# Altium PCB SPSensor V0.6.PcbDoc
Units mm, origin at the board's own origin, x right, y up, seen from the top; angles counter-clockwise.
Board outline 97.48 x 57.45 mm, 4 copper layers (TopLayer, GND, PWR, BottomLayer); 106 components, 63 nets, 343 pads, 148 vias.
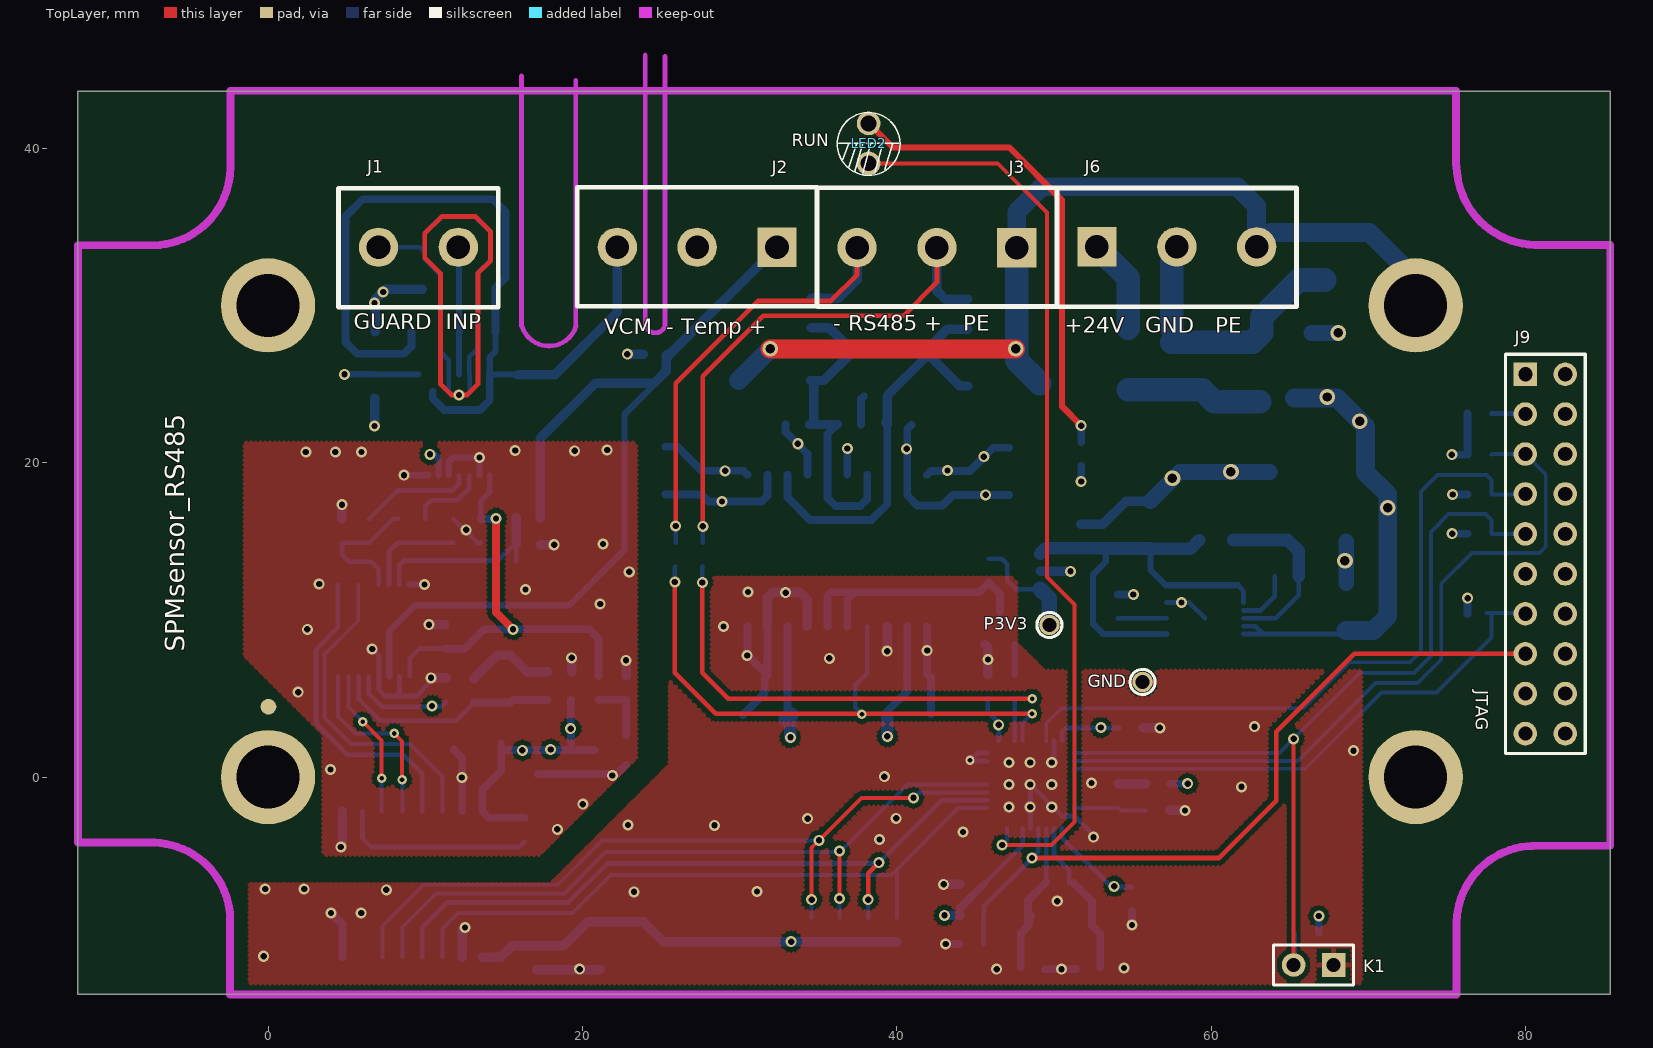
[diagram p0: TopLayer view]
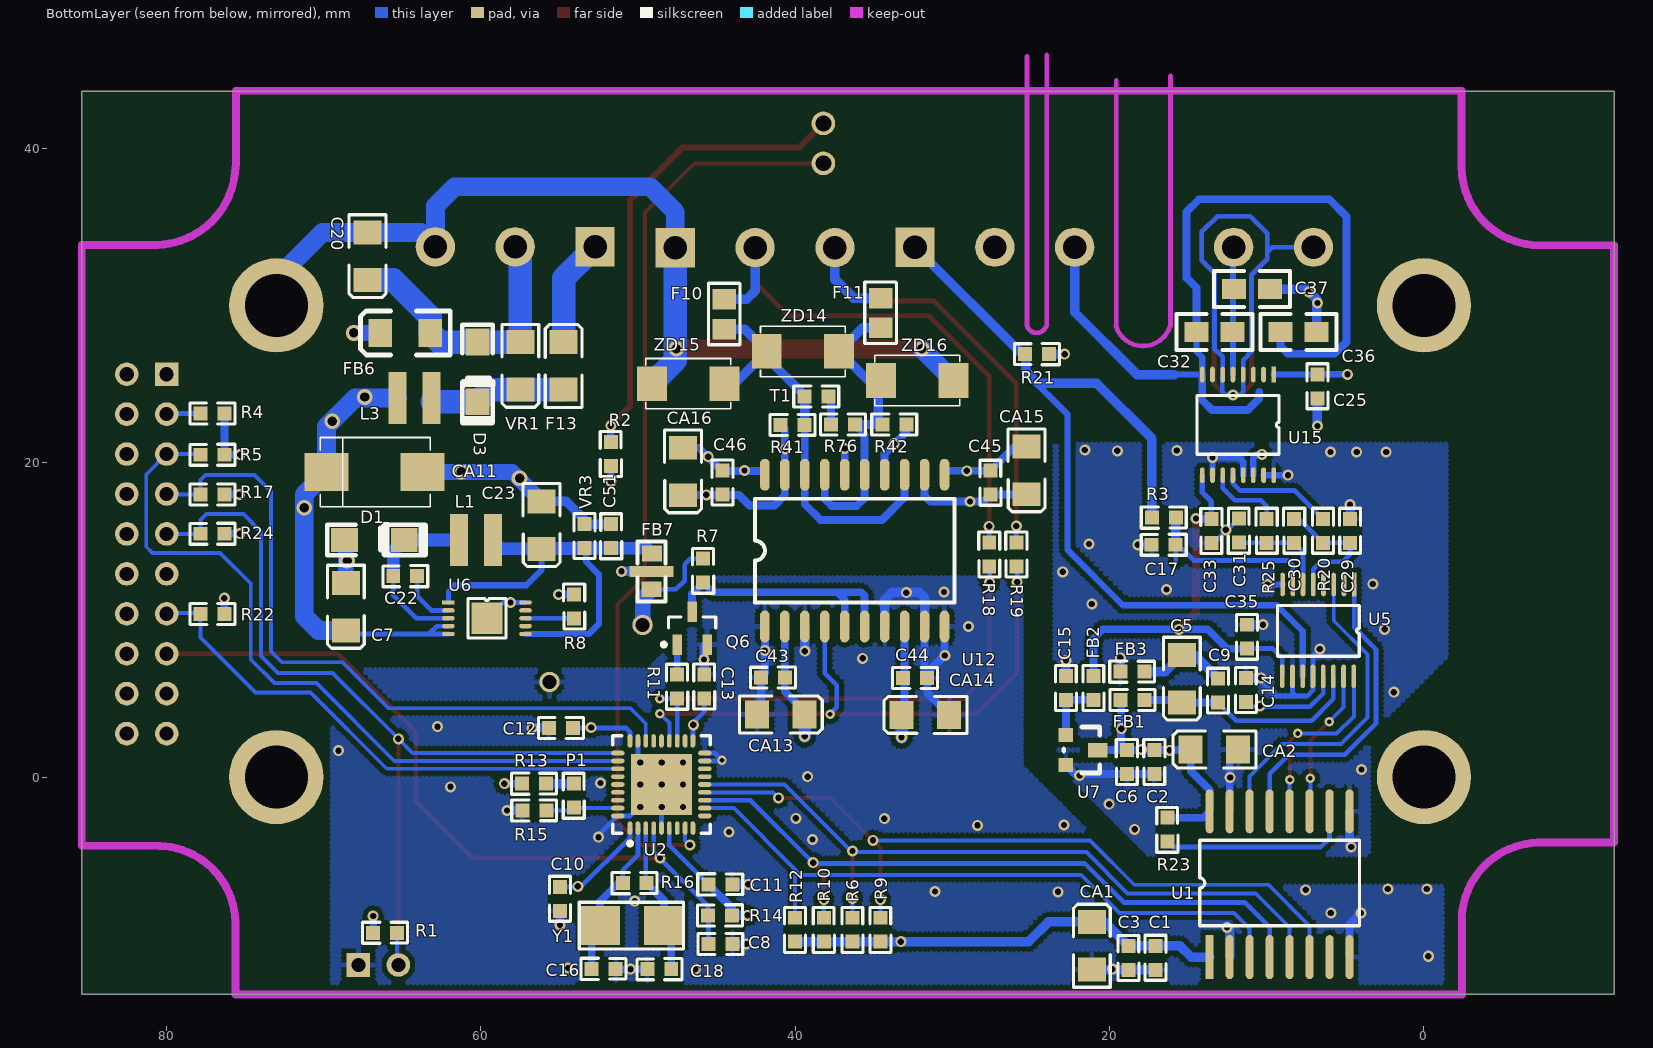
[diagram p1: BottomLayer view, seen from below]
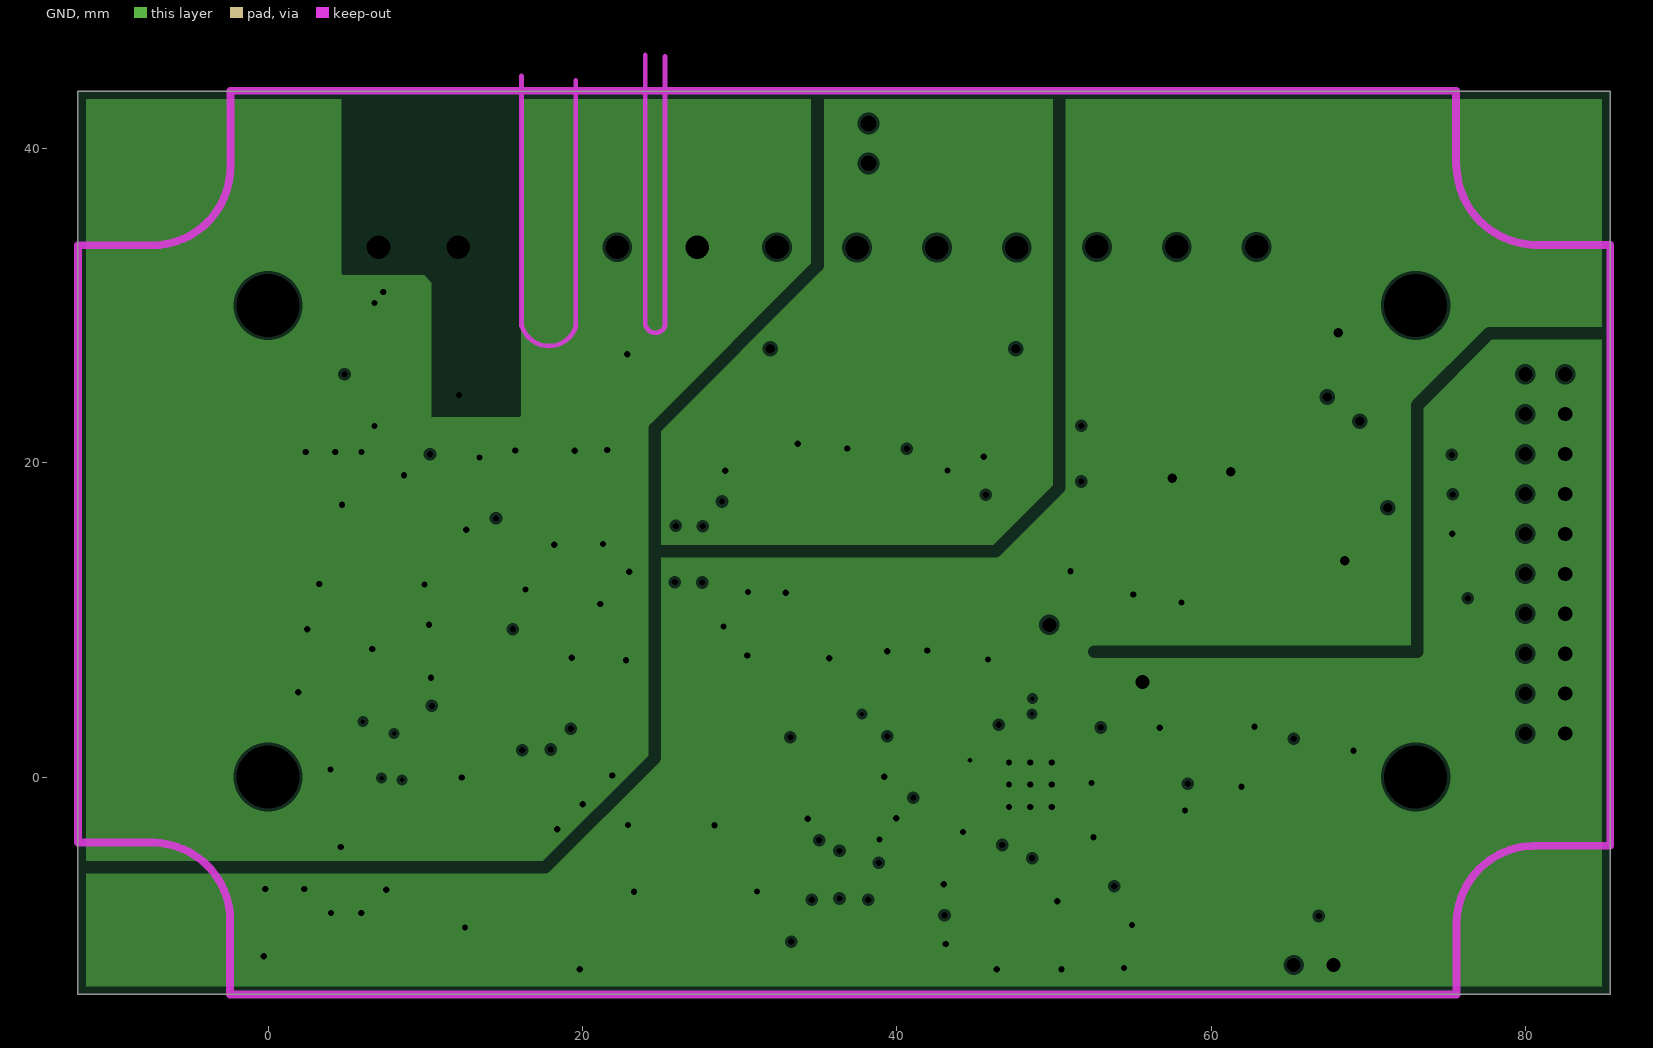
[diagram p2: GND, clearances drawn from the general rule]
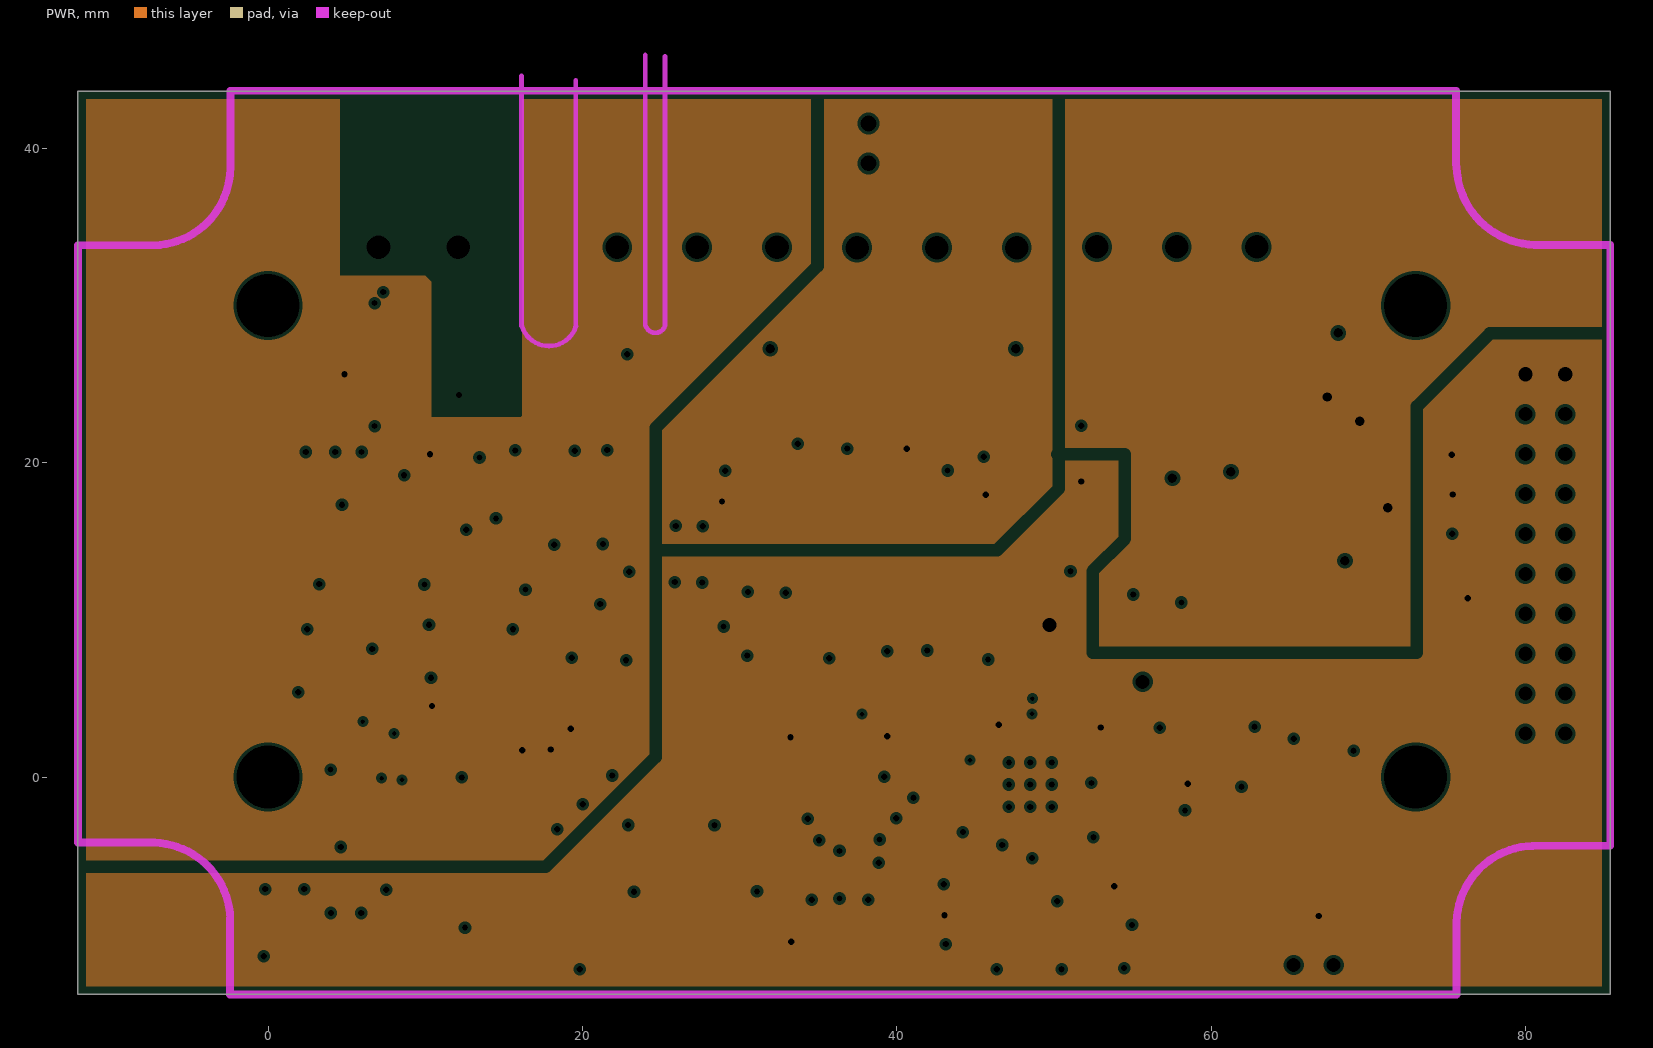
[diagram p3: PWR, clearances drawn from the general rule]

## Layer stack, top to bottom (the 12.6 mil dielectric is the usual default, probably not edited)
TopLayer: signal copper 0.0356
Dielectric: core 0.32, FR-4, Dk 4.8
GND: plane copper 0.0356, net (Multiple Nets)
Dielectric: prepreg 0.32, FR-4, Dk 4.8
PWR: plane copper 0.0356, net (Multiple Nets)
Dielectric: core 0.32, FR-4, Dk 4.8
BottomLayer: signal copper 0.0356

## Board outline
-12.1,-13.825 85.375,-13.825 85.375,43.625 -12.1,43.625

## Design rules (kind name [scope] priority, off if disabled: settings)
Clearance Clearance_poly [InPolygon] p1: gap=0.3
Clearance [All] p2: gap=0.15
ComponentClearance [All] p1: gap=0.15 collisioncheckmode=3 verticalgap=0.254 showdistances=FALSE
FabricationTestPointUsage TestPointUsage [All] p1: valid=0 allowmultiple=FALSE
FabricationTestpoint Testpoint [All] p1: side=3 testpointundercomponent=TRUE minsize=1.016 maxsize=2.54 preferedsize=1.524 minholesize=0.508 maxholesize=1.016 preferedholesize=0.813 testpointgrid=0.025 allowsidetop=TRUE allowsidebottom=TRUE usegrid=TRUE gridtolerance=0
HoleSize [All] p1: absolutevalues=TRUE maxlimit=10 minlimit=0.025 maxpercent=80.000 minpercent=20.000
MinimumSolderMaskSliver [All] p1: minsoldermaskwidth=0.15
PlaneClearance [All] p1: clearance=0.2
PlaneConnect [All] p1: planeconnectstyle=Relief reliefexpansion=0.3 reliefentries=4 reliefconductorwidth=0.3 reliefairgap=0.3
PolygonConnect PolygonConnect_via [IsVia] p1: connectstyle=Direct reliefconductorwidth=0.254 reliefentries=4 polygonreliefangle="90 Angle"
PolygonConnect [All] p2: connectstyle=Relief reliefconductorwidth=0.3 reliefentries=4 polygonreliefangle="90 Angle"
RoutingVias [All] p1: holewidth=0.305 width=0.61 viastyle="Through Hole" minholewidth=0.254 minwidth=0.508 maxholewidth=2 maxwidth=5
SilkToSilkClearance [All] p1: silktosilkclearance=0
SilkscreenOverComponentPads [All] p1: minsilkscreentomaskgap=0
SolderMaskExpansion [All] p1: expansion=0.102
Width [All] p1: maxlimit=5.08 minlimit=0.1 preferedwidth=0.254
19 further rules are at their usual default settings.

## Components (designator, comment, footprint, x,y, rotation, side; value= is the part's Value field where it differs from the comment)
C1 "10nF" SM0603 17.025,-11.5 r270 bottom
C2 "0.1uF" SM0603 17.1,0.95 r270 bottom
C3 "0.1uF" SM0603 18.85,-11.5 r90 bottom
C5 "10uF" SM1206 15.4,6.25 r270 bottom
C6 "4.7uF" SM0603 18.85,0.95 r270 bottom
C7 "4.7uF/50V" SM1206 68.575,10.825 r270 bottom
C8 "0.1uF" SM0603 44.75,-10.575 r180 bottom
C9 "0.1uF" SM0603 13.15,5.5 r90 bottom
C10 "0.1uF" SM0603 54.905,-7.75 r270 bottom
C11 "0.1uF" SM0603 44.755,-6.775 r180 bottom
C12 "0.1uF" SM0603 54.9,3.075 r0 bottom
C13 "0.1uF" SM0603 45.83,5.765 r90 bottom
C14 "0.1uF" SM0603 11.375,5.55 r90 bottom
C15 "1uF" SM0603 22.825,5.675 r90 bottom
C16 "22pF" SM0603 52.175,-12.15 r180 bottom
C17 "1uF" SM0603 16.555,14.725 r0 bottom
C18 "22pF" SM0603 48.64,-12.275 r0 bottom
C20 "1nF/2kV" SM1206 67.2,33.125 r270 bottom
C22 "0.47uF" SM0603 64.8,12.725 r0 bottom
C23 "22uF" SM1206 56.125,16.025 r270 bottom
C25 "0.1uF" SM0603 6.725,24.85 r270 bottom
C29 "1uF" SM0603 4.65,15.66 r270 bottom
C30 "100pF" SM0603 8.2,15.66 r270 bottom
C31 "1uF" SM0603 11.825,15.675 r90 bottom
C32 "1nF/2kV" 0805 12.175,28.325 r0 bottom (schematic designator C4)
C33 "0.1uF" SM0603 13.475,15.65 r270 bottom
C35 "0.1uF" SM0603 11.3,8.925 r90 bottom
C36 "1nF" 0805 9.125,28.3 r180 bottom (schematic designator C21)
C37 "1nF" 0805 12.1,31.025 r180 bottom (schematic designator C19)
C43 "0.1uF" SM0603 41.415,6.275 r0 bottom
C44 "0.1uF" SM0603 32.36,6.35 r180 bottom
C45 "0.1uF" SM0603 27.625,18.725 r90 bottom
C46 "0.1uF" SM0603 44.575,18.725 r270 bottom
C51 "0.1uF" SM0603 51.75,15.325 r90 bottom
CA1 "10uF" SM1206 21.125,-10.725 r90 bottom
CA2 "10uF" SM1206 13.325,1.75 r0 bottom
CA11 "47uF/50V" D 69.8,19.4 r180 bottom
CA13 "10uF" SM1206 40.9,3.975 r180 bottom
CA14 "10uF" SM1206 31.715,3.95 r0 bottom
CA15 "10uF" SM1206 25.275,19.5 r270 bottom
CA16 "10uF" SM1206 47.125,19.435 r270 bottom
D1 "CD1607-B140" 1206D 68.467,15.075 r180 bottom
D3 "1N4007" 1206D 60.2,27.475 r270 bottom
F10 "FUSE1" SM0805 44.475,29.425 r90 bottom
F11 "FUSE1" SM0805 34.525,29.5 r90 bottom
F13 "1A" SM1206 54.725,26.15 r90 bottom
FB1 "BLM18PG600SN1" SM0603 18.525,4.95 r180 bottom
FB2 "BLM18PG600SN1" SM0603 21.075,5.675 r90 bottom
FB3 "BLM18PG600SN1" SM0603 18.55,6.75 r180 bottom
FB6 "BLM31PG500SN1" 1206 66.25,28.25 r0 bottom
FB7 "NFM21PC105B1C3" NFM21PC105 49.125,14.225 r270 bottom
GND "TestPoint" "test point" 55.625,6.05 r90 top
J1 "PH2-5.08mm" PH2-5.08mm 7.025,33.7 r0 top
J2 "PH3-5.08mm" PH3-5.08mm 32.375,33.7 r180 top
J3 "PH3-5.08mm" PH3-5.08mm 47.625,33.675 r180 top
J6 "PH3-5.08mm" PH3-5.08mm 52.725,33.725 r0 top
J9 "JTAG" HDR2X10 79.975,25.625 r270 top
K1 "KEY1" HDR1x2 67.775,-11.955 r180 top (schematic designator R1)
L1 "LPS3010-472ML" LPS3010 61.385,15.075 r180 bottom
L3 "LPS3010-472ML" LPS3010 63.125,24.1 r0 bottom
LED2 "RUN" LED 38.2,41.575 r270 top
P1 "NC" sm0603 54.13,-1.185 r90 bottom
P3V3 "TestPoint" "test point" 49.7,9.675 r90 top
Q6 "MMBT3904" SOT23_N 46.55,9.475 r90 bottom
R1 "10K" SM0603 66.075,-9.855 r180 bottom
R2 "560R" SM0603 51.775,20.55 r90 bottom
R3 "10K" SM0603 16.54,16.55 r180 bottom
R4 "10K" SM0603 77.065,23.075 r0 bottom
R5 "10K" SM0603 77.065,20.45 r0 bottom
R6 "100K" SM0603 36.401,-9.713 r90 bottom
R7 "4.7K" SM0603 45.9,13.125 r90 bottom
R8 "49.9K" SM0603 54,10.85 r270 bottom
R9 "100K" SM0603 34.626,-9.713 r90 bottom
R10 "100K" SM0603 38.226,-9.713 r90 bottom
R11 "1K" SM0603 47.555,5.75 r90 bottom
R12 "100K" SM0603 40.051,-9.713 r90 bottom
R13 "1K" SM0603 56.605,-0.375 r180 bottom
R14 "10K" SM0603 44.775,-8.85 r0 bottom
R15 "100K" SM0603 56.59,-2.075 r180 bottom
R16 "10M" SM0603 50.2,-6.7 r180 bottom
R17 "10K" SM0603 77.065,17.925 r0 bottom
R18 "0R" SM0603 27.6,14.15 r270 bottom
R19 "0R" SM0603 25.875,14.15 r270 bottom
R20 "10K" SM0603 6.375,15.66 r270 bottom
R21 "NC" SM0603 24.625,26.85 r0 bottom
R22 "10K" SM0603 77.065,10.325 r0 bottom
R23 "4.7K" SM0603 16.375,-3.35 r90 bottom
R24 "NC" SM0603 77.065,15.425 r0 bottom
R25 "10K" SM0603 9.95,15.66 r270 bottom
R41 "47K" SM0603 40.16,22.45 r180 bottom
R42 "47K" SM0603 33.685,22.475 r180 bottom
R76 "120R" SM0603 36.965,22.375 r0 bottom
T1 "" SM0603 38.65,24.25 r180 bottom
U1 "ADuM5401ARWZ" ADUM1401 13.625,-11.45 r90 bottom locked
U2 "STM32F103T8U6" VFQN36_V 48.5,-0.475 r90 bottom locked
U5 "AD7793BRU" AD7793 6.725,9.325 r270 bottom
U6 "LT3971IMSE-3.3" LT3971 59.6,10.1 r270 bottom
U7 "AD1584BRTZ" SOT-23 20.63,0.339 r270 bottom
U12 "ADM2587E" SOL-20 41.925,9.575 r90 bottom
U15 "LMP91200" LMP91200 11.825,22.4 r0 bottom
VR1 "V42MLA1206N" SM1206 57.475,26.15 r270 bottom
VR3 "V3.5MLA0603N" SM0603 53.35,15.325 r270 bottom (schematic designator VA2)
Y1 "8MHz" CY5.4X4.6 52.375,-9.45 r180 bottom
ZD14 "SMBJ12" ZD 41.8,27.075 r180 bottom
ZD15 "SMBJ12" ZD 44.5,25.025 r0 bottom
ZD16 "SMBJ12" ZD 29.925,25.225 r0 bottom

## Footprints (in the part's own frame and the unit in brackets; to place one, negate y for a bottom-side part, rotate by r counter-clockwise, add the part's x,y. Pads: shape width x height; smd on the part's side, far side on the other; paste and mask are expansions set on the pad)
0805 [mil]
  rect 60x50 smd: 1(0.39,0.31) 2(90.39,0.31)
  silkscreen extent -50,-45 140,45
1206 [mm]
  rect 1.5x1.8 smd: 1(-3.048,0) 2(0.127,0)
  silkscreen extent -4.32,-1.4 1.4,1.4
1206D [mm]
  rect 1.7x1.524 smd: 1(-0.19,0.003) 2(3.61,0.003)
  silkscreen extent -1.3,-0.97 4.96,0.99
AD7793 [mm]
  rect 1.5x0.3 smd: 1(-2.921,2.286)
  oval 1.5x0.3 smd: 2(-2.921,1.636) 3(-2.921,0.986) 4(-2.921,0.336) 5(-2.921,-0.314) 6(-2.921,-0.964) 7(-2.921,-1.614) 8(-2.921,-2.264) 9(2.921,-2.286) 10(2.921,-1.636) 11(2.921,-0.986) 12(2.921,-0.336) 13(2.921,0.314) 14(2.921,0.964) 15(2.921,1.614) 16(2.921,2.264)
  silkscreen extent -1.59,-2.59 1.64,2.61
ADUM1401 [mm]
  rect 2.8x0.51 smd: 1(0,0)
  oval 2.8x0.51 smd: 2(0,-1.27) 3(0,-2.54) 4(0,-3.81) 5(0,-5.08) 6(0,-6.35) 7(0,-7.62) 8(0,-8.89) 9(9.271,-8.89) 10(9.271,-7.62) 11(9.271,-6.35) 12(9.271,-5.08) 13(9.271,-3.81) 14(9.271,-2.54) 15(9.271,-1.27) 16(9.271,0)
  silkscreen extent 1.99,-9.53 7.43,0.63
CY5.4X4.6 [mm]
  rect 2.5x2.5 smd: 1(-0.025,0) 2(4,0)
  silkscreen extent -1.35,-1.49 5.28,1.49
D [mil]
  rect 110x94.49 smd: 1(0,0) 2(240,0)
  silkscreen extent -16,-87 260,87
HDR1x2 [mm] "Connector; Header; 2 Position"
  rect 1.5x1.5 hole 0.9: 1(0,0)
  round 1.5 hole 0.9: 2(2.54,0)
  silkscreen extent -1.27,-1.27 3.81,1.27
HDR2X10 [mm] "Connector; Header; 10x2 Position"
  rect 1.5x1.5 hole 0.9: 1(0,0)
  round 1.5 hole 0.9: 2(0,2.54) 3(2.54,0) 4(2.54,2.54) 5(5.08,0) 6(5.08,2.54) 7(7.62,0) 8(7.62,2.54) 9(10.16,0) 10(10.16,2.54) 11(12.7,0) 12(12.7,2.54) 13(15.24,0) 14(15.24,2.54) 15(17.78,0) 16(17.78,2.54) 17(20.32,0) 18(20.32,2.54) 19(22.86,0) 20(22.86,2.54)
  silkscreen extent -1.27,-1.27 24.13,3.81
LED [mm]
  round 1.5 hole 1: 1(0,0) 2(2.54,0)
  silkscreen extent -0.7,-2 3.3,2
LMP91200 [mm]
  rect 0.3x1 smd: 1(-2.275,-3.2)
  oval 0.3x1 smd: 2(-1.625,-3.2) 3(-0.975,-3.2) 4(-0.325,-3.2) 5(0.325,-3.2) 6(0.975,-3.2) 7(1.625,-3.2) 8(2.275,-3.2) 9(2.275,3.2) 10(1.625,3.2) 11(0.975,3.2) 12(0.325,3.2) 13(-0.325,3.2) 14(-0.975,3.2) 15(-1.625,3.2) 16(-2.275,3.2)
  silkscreen extent -2.6,-1.87 2.6,1.87
LPS3010 [mm]
  rect 1.14x3.3 smd: 1(0,0) 2(2.16,0)
LT3971 [mm]
  rect 0.28x0.8 smd: 1(-1,-2.45)
  oval 0.28x0.8 smd: 2(-0.5,-2.45) 3(0,-2.45) 4(0.5,-2.45) 5(1,-2.45) 6(1,2.45) 7(0.5,2.45) 8(0,2.45) 9(-0.5,2.45) 10(-1,2.45)
  rect 2x2 smd: 11(0,0)
  silkscreen extent -1.25,-1.21 1.25,1.22
NFM21PC105 [mm]
  rect 1x1.27 smd: 1(0.01,0.008) 2(2.286,0)
  rect 0.7x2.8 smd: 3(1.143,0)
  silkscreen extent -0.76,-0.89 3.05,0.89
PH2-5.08mm [mm]
  round 2.5 hole 1.5: 1(0,0) 2(5.08,0)
  silkscreen extent -2.54,-3.81 7.62,3.75
PH3-5.08mm [mm]
  rect 2.5x2.5 hole 1.5: 1(0,0)
  round 2.5 hole 1.5: 2(5.08,0) 3(10.16,0)
  silkscreen extent -2.54,-3.81 12.7,3.75
SM0603 [mil]
  rect 35x35 smd: 1(-30,-2) 2(30,-2)
  silkscreen extent -57,-28 56,24
sm0603 [mil]
  rect 35x35 smd: 1(-30,-2) 2(30,-2)
  silkscreen extent -57,-28 56,24
SM0805 [mm]
  rect 1.3x1.5 smd: 1(-0.933,0.022) 2(0.967,0.022)
  silkscreen extent -1.93,-0.97 1.98,1.04
SM1206 [mil]
  rect 60x70 smd: 1(59.5,0) 2(-59.5,0)
  silkscreen extent -104,-46 104,46
SOL-20 [mil]
  oval 80x24 smd: 1(0,0) 2(0,-50) 3(0,-100) 4(0,-150) 5(0,-200) 6(0,-250) 7(0,-300) 8(0,-350) 9(0,-400) 10(0,-450) 11(380,-450) 12(380,-400) 13(380,-350) 14(380,-300) 15(380,-250) 16(380,-200) 17(380,-150) 18(380,-100) 19(380,-50) 20(380,0)
  silkscreen extent 60,-475 320,25
SOT23_N [mm] "SOT23, 3-Leads, Body 2.9x1.3mm, Pitch 0.95mm, Lead Span 2.3mm, IPC Medium Density"
  rect 1.3x0.6 smd: 1(-1.05,0.95) 2(-1.05,-0.95) 3(1.05,0)
  silkscreen extent -1.17,-1.5 0.7,1.93, body extent -0.7,-1.5 0.7,1.5, height 1.1
SOT-23 [mil]
  rect 36x36 smd: 1(-91.86,-84.66) 2(-16.86,-84.66)
  rect 36x50 smd: 3(-53.86,-4.66)
  silkscreen extent -112,-90 3,0
"test point" [mm]
  round 1.3 hole 0.9: 1(0,0)
  silkscreen extent -0.8,-0.8 0.8,0.8
VFQN36_V [mm] "QFN, 36-Leads, Body 6x6mm, Pitch 0.5mm, ST Recommended"
  oval 0.85x0.3 smd: 1(-2.775,2) 2(-2.775,1.5) 3(-2.775,1) 4(-2.775,0.5) 5(-2.775,0) 6(-2.775,-0.5) 7(-2.775,-1) 8(-2.775,-1.5) 9(-2.775,-2) 19(2.775,-2) 20(2.775,-1.5) 21(2.775,-1) 22(2.775,-0.5) 23(2.775,0) 24(2.775,0.5) 25(2.775,1) 26(2.775,1.5) 27(2.775,2)
  oval 0.3x0.85 smd: 10(-2,-2.755) 11(-1.5,-2.755) 12(-1,-2.755) 13(-0.5,-2.755) 14(0,-2.755) 15(0.5,-2.755) 16(1,-2.755) 17(1.5,-2.755) 18(2,-2.755) 28(2,2.775) 29(1.5,2.775) 30(1,2.775) 31(0.5,2.775) 32(0,2.775) 33(-0.5,2.775) 34(-1,2.775) 35(-1.5,2.775) 36(-2,2.775)
  rect 3.9x3.9 smd: 37(0,0)
  silkscreen extent -3.87,-3.1 3.1,3.1, body extent -3.05,-3.05 3.05,3.05, height 1
ZD [mm]
  rect 1.9x2.2 smd: 1(0,0) 2(4.6,0)
  silkscreen extent -0.4,-1.6 5,1.6

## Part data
C1 C6 C7 C9 C14 C15 C17 C20 C22 C25 C29 C30 C31 C32 C33 C35 C36 C37 C51: library part CAP, "Capacitor"
C2 C3 C43 C44 C45 C46: library part CAP, "电?"
C5 CA11 CA13 CA14 CA15 CA16: library part CAPE, "极性"
C8: library part Cap, "Capacitor, X7R Ceramic"
C10 C11 C12 C13 C16 C18: library part Cap, "Capacitor"
C23: library part C, "极性"
CA1 CA2: library part CAPE, "Capacitor"
D1: library part DIODE, "Diode"
D3: library part "Diode 1N4007", "1 Amp General Purpose Rectifier"
F10 F11: "Fuse"
F13: library part FUSE1, "Fuse"
FB1 FB3 L1 L3: library part INDUCTOR
FB2 FB6 FB7: library part Inductor, "Inductor"
J1 K1: library part "Header 2", "Header, 2-Pin"
J2 J3 J6: library part CON3, "Connector"
J9: library part "Header 10X2", "Header, 10-Pin, Dual row"
LED2: library part LED0, "Typical INFRARED GaAs LED"
P1: library part Hea, "Header, 2-Pin, 2.54mm, 排?"
Q6: "NPN Switching Transistor"
R1 R2 R7 R11 R16 R18 R19: library part Res2, "Resistor"
R3 R4 R5 R6 R9 R10 R12 R17 R20 R21 R22 R24 R25: library part R, "电?"
R8 R13 R14 R15 R23 R41 R42 R76: library part RES, "电?"
T1: library part CON2, "Connector"
U1: library part ADUM1401, "1Mbps Data Rate, 100ns Propagation delay"
U2: "STM32 ARM-based 32-bit MCU with 64 Kbytes Flash, 36-pin VFQFPN, Industrial Temperature"
U5: library part AD7793
U6: library part LT3971
U7: library part "Header 3", "4.096V reference"
VR1: library part "Res Varistor", "Varistor (Voltage-Sensitive Resistor)"
VR3: library part "D Zener", "Zener Diode"
Y1: library part XTAL, "Crystal Oscillator"
ZD14 ZD15 ZD16: library part SMBJ, "Ë²±äÒ"

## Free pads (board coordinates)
  round 1 smd: 0(0.025,4.475)
  round 6 hole 4: 3(73,30) 4(73,0) 5(0,0) 6(0,30)

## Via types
v1: diameter 0.7, hole 0.4, TopLayer to BottomLayer, 131 vias
v2: diameter 1, hole 0.6, TopLayer to BottomLayer, 9 vias
v3: diameter 0.6, hole 0.3, TopLayer to BottomLayer, 8 vias

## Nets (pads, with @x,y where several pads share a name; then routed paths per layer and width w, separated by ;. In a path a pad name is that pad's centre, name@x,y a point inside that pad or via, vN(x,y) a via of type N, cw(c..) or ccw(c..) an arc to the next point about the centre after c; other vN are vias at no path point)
24VGND_IN: C20.1 D3.1 FB6.1 J6.2 VR1.2 | length 17.8
  BottomLayer w1.5: VR1.2 60.193,27.661 D3.1 62.617,27.665 FB6.1 63.202,29.252 65.564,31.614 C20.1 ; 57.475,28.536 57.475,33.395 J6.2 J6.2@58.147,33.383
+24V: C7.1 CA11.1 L3.2 U6.4 U6.5 | length 29
  BottomLayer w0.3: U6.5 63.3,9.1 ; U6.4 62.8,9.6 63.3,9.1 ; C7.1 68.361,9.1 63.3,9.1
  BottomLayer w1.2: L3.2 68,24.1 69.8,22.3 CA11.1 71.225,17.975 71.225,10.225 70.314,9.314 C7.1
  other v2: 71.225,17.125 69.45,22.625 67.375,24.175
+24V_IN: F13.1 J6.1 | length 6.1
  BottomLayer w1.5: J6.1@52.675,33.675 J6.1 54.725,31.725 54.725,28.536
BOOT0: P1.1 R15.2 U2.35 | length 4.6
  BottomLayer w0.25: U2.35 54.052,-1.975 P1.1 54.258,-2.126 R15.2
DE485: Q6.3 R7.1 U12.5 U12.6 | length 17.1
  BottomLayer w0.5: U12.6 35.575,11.525 35.8,11.75 37.325,11.75 ; U12.5 36.845,11.27 37.325,11.75 ; Q6.3 46.55,11.662 R7.1 45.236,11.75 37.325,11.75
DVDD: C5.1 C9.1 FB1.2 U5.14 | length 14.6
  BottomLayer w0.3: U5.14 5.761,4.964 7.15,3.575 11.936,3.575 C9.1
  BottomLayer w0.5: C9.1 C5.1 15.561,4.899 FB1.2
EARTH: C20.2 J3.1 J6.3 pad.3 ZD15.2 ZD16.1 | length 62.5
  TopLayer w1.2: v2(31.938,27.237) v2(47.562,27.237)
  BottomLayer w1.2: ZD16.1 v2(31.938,27.237) ; J3.1 47.625,35.95 49.225,37.55 61.65,37.55 62.885,36.315 J6.3 63.796,34.636 C20.2 70.064,34.636 73,31.7 pad.3
  BottomLayer w1.5: J3.1@47.675,33.625 J3.1 47.625,26.5 ZD15.2
GND: C1.2 C3.1 C7.2 C8.2 C10.2 C11.2 C12.2 C13.2 C16.2 C18.2 C23.2 C43.2 C44.2 C51.2 CA1.2 CA11.2 CA13.2 CA14.2 D1.1 FB6.2 FB7.3 GND.1 J9.4 J9.6 J9.8 J9.10 J9.12 J9.14 J9.16 J9.18 J9.20 K1.1 Q6.2 R8.1 R15.1 R24.1 U1.2 U1.8 U2.5 U2.17 U2.18 U2.26 U2.36 U2.37 U6.10 U6.11 U12.1 U12.3 U12.7 U12.9 U12.10 VR3.1 | length 77.7
  TopLayer w0.3: v1@52.35,-0.375 v1(52.375,-0.375)
  BottomLayer w0.3: U2.17 44.7,1.025 v3(44.65,1.075) 45.1,1.525 U2.18 ; U2.5 U2.37 50.5,-2.475 U2.36 v1@52.475,-3.675 ; U2.37@50,1.025 U2.26 ; U6.10 58.6,11.1 U6.11
  BottomLayer w0.5: v1(4,-8.65) 4.735,-9.385 U1.8 ; CA14.2 31.598,5.345 C44.2 C44.2@31.765,6.466 ; U12.10 30.495,7.736 C44.2@31.765,6.466 ; U12.9 C44.2@31.765,6.466 ; U12.1 41.925,6.578 C43.2 CA13.2@42.177,4.009 ; v1(43.101,-10.626) C8.2 ; C18.2 v1(50.475,-12.224) 51.39,-12.224 C16.2 ; R8.1 v1(55.038,11.612) ; v1(54.956,-9.406) C10.2 ; v1(75.324,15.476) R24.1
  BottomLayer w0.6: U1.2 12.355,-9.745 v1(12.525,-9.575) ; C1.2 21.099,-12.262 CA1.2 ; U12.9 31.765,11.415 32.1,11.75 33.825,11.75 34.305,11.27 U12.7 ; v1(39.385,8.01) U12.3 ; v1(42.976,-6.826) C11.2 ; Q6.2 45.779,8.246 C13.2 ; FB7.3 v1(51.043,13.082) ; C51.2 53.112,16.087 54.561,17.536 C23.2 ; C12.2 v1(56.724,3.126) ; R15.1 v1(58.326,-2.126)
  BottomLayer w1: C23.2 57.989,19.4 CA11.2 ; FB6.2 v2(68.075,28.25) ; C7.2 D1.1@68.575,14.995
  other v1: 19.825,-12.225 46.35,-12.225 54.45,-12.15 -0.275,-11.4 5.925,-8.65 50.2,-7.9 23.275,-7.3 31.1,-7.275 7.525,-7.175 -0.181,-7.125 2.3,-7.125 38.9,-3.975 52.5,-3.825 44.2,-3.5 28.4,-3.075 22.9,-3.05 34.325,-2.65 39.95,-2.625 47.125,-1.9 48.475,-1.9 49.85,-1.9 61.919,-0.625 47.125,-0.475 48.475,-0.475 49.85,-0.475 39.2,0.025 47.125,0.925 48.475,0.925 49.85,0.925 69.05,1.675 62.75,3.2 45.8,7.475 35.7,7.55 30.475,7.725 41.925,8.05 28.975,9.575 58.1,11.1 32.925,11.725 30.525,11.775
  other v2: 68.5,13.75 57.525,19 61.25,19.425
GND_COM: C45.2 C46.1 CA15.2 CA16.2 R42.2 U12.11 U12.14 U12.16 U12.20 | length 17.3
  BottomLayer w0.5: CA15.2 26.05,21.011 C45.2 30.235,19.487 U12.11 ; R42.2 32.923,21.952 34.305,20.57 U12.14 ; U12.16 v1(36.845,20.895) ; U12.20 42.16,19.462 C46.1@44.651,19.462 ; C46.1@44.651,19.462 46.135,20.947 CA16.2
  other v1: 29.075,19.475 43.225,19.5 45.525,20.375 33.7,21.2
GND_ISO: C2.2 C6.2 C14.2 C15.2 C17.2 C25.2 C29.1 C31.2 C33.2 C35.2 C36.2 C37.2 CA2.2 FB3.1 J2.2 R21.1 U1.9 U1.15 U5.8 U5.10 U5.12 U7.2 U15.10 U15.13 U15.15 U15.16 | length 43.3
  BottomLayer w0.3: v1(6.625,8.15) 7.061,7.714 U5.12 7.061,5.514 7.425,5.15 8.125,5.15 ; U5.10 8.361,5.386 8.125,5.15 ; v1(10.362,6.312) 10.362,6.087 9.425,5.15 8.125,5.15 ; C31.2 13.323,14.888 C33.2
  BottomLayer w0.4: v1(8.65,19.2) U15.16 U15.15 ; U5.8 v1(9.946,12.246) ; U15.13 11.5,20.05 11.775,20.325 v1(13.45,20.325) U15.10
  BottomLayer w0.5: CA2.2 12.355,1.209 U1.15 ; C2.2 C6.2 22.202,0.188 U7.2
  BottomLayer w0.6: v1(4.625,-4.45) 4.735,-4.34 U1.9 ; C29.1 v1(4.701,17.324) ; v1(6.776,22.326) C25.2 ; C36.2 6.829,30.404 7.458,31.033 C37.2 ; v1(10.237,9.687) C35.2 ; v1(10.362,6.312) C14.2 ; C17.2 v1(18.201,14.776) ; FB3.1 v1(19.312,7.587) ; C15.2 v1(22.774,7.424) ; v1(22.849,26.901) R21.1
  other v1: 18.4,-3.325 20.025,-1.725 12.325,-0.025 21.9,0.1 3.975,0.475 1.919,5.4 2.5,9.4 21.125,11 16.375,11.925 3.25,12.275 22.975,13.05 21.3,14.825 12.6,15.725 2.4,20.675 4.275,20.675 5.95,20.675 19.5,20.75 15.719,20.775 21.575,20.8 6.775,30.15 7.325,30.85
GUARD: J1.1 U15.4 U15.6 | length 59
  TopLayer w0.3: 9.975,33.025 9.975,34.575 11.05,35.65 13.2,35.65 14.15,34.7 14.15,32.85 13.35,32.05 13.35,25 12.65,24.3 v1(12.15,24.3) 11.675,24.3 10.975,25 10.975,32.025 9.975,33.025
  BottomLayer w0.3: J1.1 9.65,33.7 9.975,33.375 ; U15.6 12.8,26.725 13.325,27.25 13.325,32.075 14.125,32.875 14.125,34.675 13.125,35.675 11.05,35.675 9.975,34.6 9.975,33.375 ; U15.6@12.825,25.6 12.825,24.5 12.625,24.3 v1(12.15,24.3) 11.7,24.3 11.5,24.5 U15.4 11.5,26.525 10.975,27.05 10.975,31.925 9.975,32.925 9.975,33.375
JNTRST: J9.3 R4.2 | length 2.2
  BottomLayer w0.3: R4.2 79.934,23.126 J9.3
JTCK: J9.9 K1.2 R1.2 R24.2 U2.28 | length 57.1
  TopLayer w0.25: K1.2 v1(65.235,2.435)
  BottomLayer w0.25: U2.28 64.325,1.525 v1(65.235,2.435) 69.425,6.625 72.9,6.625 73.975,7.7 73.975,15.6 75.1,16.725 77.45,16.725 77.827,16.348 R24.2 77.838,15.465 J9.9 ; K1.2 65.313,-11.877 R1.2
JTDI: J9.5 R5.2 U2.29 | length 47.1
  BottomLayer w0.25: U2.29 65.5,1.025 70.45,5.975 73.125,5.975 74.625,7.475 74.625,12.3 76.575,14.25 80.875,14.25 81.275,14.65 81.275,19.245 J9.5 77.871,20.545 R5.2
JTDO: J9.13 R22.2 U2.30 | length 34
  BottomLayer w0.25: U2.30 65.975,0.525 70.825,5.375 74.327,5.375 77.502,8.55 77.827,8.875 R22.2 ; R22.2@77.502,10.426 79.934,10.426 J9.13
JTMS: J9.7 R17.2 U2.25 | length 45.2
  BottomLayer w0.25: U2.25 49.5,3.4 50.475,4.375 65.875,4.375 68.8,7.3 72.65,7.3 73.325,7.975 73.325,18.15 74.4,19.225 77.5,19.225 77.827,18.898 R17.2 79.946,17.976 J9.7
JTRST: U2.31
KEY1: U2.24
LED_S1: U2.23
LED_S2: LED2.2 U2.8 | length 58.5
  TopLayer w0.25: LED2.2 46.415,39.035 49.55,35.9 49.55,12.725 51.3,10.975 51.3,-2.85 49.825,-4.325 v1(46.7,-4.325)
  BottomLayer w0.25: v1(46.7,-4.325) 47,-4.025 U2.8
MCU_RXD1: R19.2 U2.22 U12.4 | length 38.6
  TopLayer w0.3: v1(25.875,12.4) 25.875,6.625 28.475,4.025 v3(48.6,4.025)
  BottomLayer w0.25: R19.2@25.875,13.337 R19.2 ; U2.22 48,3.425 v3(48.6,4.025)
  BottomLayer w0.3: v1(25.875,12.4) R19.2@25.875,13.337 ; v3(37.775,4) 37.35,4.425 37.35,5.85 38.115,6.615 U12.4
MCU_TXD1: R11.1 R18.2 U2.21 | length 32.2
  TopLayer w0.3: v1(27.625,12.375) 27.625,6.625 29.262,4.988 v3(48.613,4.988)
  BottomLayer w0.3: v1(27.625,12.375) 27.625,13.362 R18.2 ; U2.21 R11.1@47.5,4.983 ; R11.1 v3(48.613,4.988)
MISO1: R9.2 U1.6 U2.13 | length 49.1
  TopLayer w0.25: v1(34.575,-7.8) 34.575,-4.5 v1(35.05,-4.025) 37.75,-1.325 v1(41.05,-1.325)
  BottomLayer w0.25: U1.6 7.275,-9.475 9.9,-6.85 18.425,-6.85 21.25,-4.025 v1(35.05,-4.025) ; R9.2 v1(34.575,-7.8) ; v1(41.05,-1.325) 41.4,-0.975 U2.13
MOSI1: R6.2 U1.5 U2.14 | length 47.1
  TopLayer w0.25: v1(36.35,-7.725) v1(36.35,-4.7)
  BottomLayer w0.25: U1.5 8.545,-9.555 10.7,-7.4 18.85,-7.4 21.475,-4.775 36.375,-4.775 40.675,-0.475 U2.14 ; R6.2 v1(36.35,-7.725)
NetC5_2: C5.2 C9.2 FB3.2 | length 5.7
  BottomLayer w0.6: C9.2 14.599,7.761 C5.2 16.462,6.699 FB3.2
NetC15_1: C15.1 FB2.1 U7.1 | length 4
  BottomLayer w0.5: FB2.1 C15.1 22.774,2.678 U7.1
NetC16_1: C16.1 R16.1 U2.2 Y1.1 | length 9.9
  BottomLayer w0.3: U2.2 50,-4.97 50.962,-5.932 R16.1
  BottomLayer w0.5: R16.1@51.251,-6.751 52.4,-7.9 Y1.1 52.937,-9.987 C16.1@52.937,-12.076
NetC17_1: C17.1 R3.2 U5.7 | length 12.1
  BottomLayer w0.3: U5.7 8.339,13.464 8.65,13.775 14.65,13.775 C17.1@15.793,14.918 ; 15.793,13.693 C17.1
  BottomLayer w0.6: C17.1@15.778,14.79 R3.2
NetC18_1: C18.1 R16.2 U2.3 Y1.2 | length 10.2
  BottomLayer w0.3: R16.2@49.5,-6.689 U2.3
  BottomLayer w0.5: C18.1@47.878,-12.099 47.878,-9.947 Y1.2 Y1.2@48.525,-8.814 ; Y1.2@48.338,-9.413 48.338,-7.851 R16.2@49.5,-6.689
NetC22_1: C22.1 U6.2 | length 3.6
  BottomLayer w0.3: U6.2 63.15,10.6 64.038,11.488 C22.1
NetC22_2: C22.2 D1.2 L1.1 U6.3 | length 11.4
  BottomLayer w0.3: U6.3 64.1,10.1 65.562,11.562 C22.2
  BottomLayer w0.8: L1.1 61.388,15.078 D1.2 65.562,14.373 C22.2
NetC23_1: C23.1 C51.1 FB7.1 L1.2 U6.1 U6.6 VR3.2 | length 28.9
  BottomLayer w0.3: 61.675,12.2 62.05,11.825 U6.1
  BottomLayer w0.4: VR3.2@53.287,14.526 53.287,13.687 52.475,12.875 52.475,9.75 53.125,9.1 U6.6 ; C23.1 56.125,13.175 57.1,12.2 61.675,12.2
  BottomLayer w0.8: FB7.1 49.465,14.563 C51.1 VR3.2 ; VR3.2@53.626,14.538 56.101,14.538 C23.1 58.664,14.514 L1.2
NetC29_2: C29.2 C30.1 R20.2 U5.5 | length 8.6
  BottomLayer w0.3: U5.5 7.039,13.211 6.55,13.7 5.175,13.7 4.701,14.174 C29.2 R20.2 7.95,16.422 C30.1
NetC30_2: C30.2 C31.1 R25.2 U5.6 | length 6.4
  BottomLayer w0.3: U5.6 7.689,14.336 C30.2 R25.2 11.759,14.898 C31.1
NetD3_2: D3.2 F13.2 L3.1 VR1.1 | length 8.7
  BottomLayer w1.5: F13.2 VR1.1 59.424,24.639 D3.2 L3.1@63.09,23.865
NetF10_1: F10.1 R41.2 T1.1 U12.13 U12.18 ZD14.1 ZD15.1 | length 26.6
  BottomLayer w0.5: U12.13 33.035,17.79 34.475,16.35 38.375,16.35 39.385,17.36 U12.18 39.385,22.412 R41.2@39.237,22.56
  BottomLayer w0.6: R41.2@39.385,22.412 R41.2 39.398,24.185 T1.1 39.412,24.287 41.8,26.675 ZD14.1 ; F10.1 43.217,28.492 ZD14.1 ; ZD15.1@44.5,24.875 44,24.875 ZD14.1
NetF11_1: F11.1 R42.1 R76.1 U12.15 U12.17 ZD14.2 ZD16.2 | length 20.7
  BottomLayer w0.5: R76.1 36.201,22.424 35.575,21.798 U12.15 35.575,17.75 36.075,17.25 37.675,17.25 38.115,17.69 U12.17
  BottomLayer w0.6: R42.1 R76.1@36.201,22.424 ; F11.1 35.708,28.567 ZD14.2 35.35,25.225 ZD16.2 34.7,25.05 R42.1@34.7,22.424
NetLED2_1: LED2.1 R2.2 | length 30.2
  TopLayer w0.4: LED2.1 39.725,40.05 47.15,40.05 50.5,36.7 50.5,23.575 v1(51.724,22.351)
  BottomLayer w0.5: R2.2 v1(51.724,22.351)
NetP1_2: P1.2 R13.2 | length 1.8
  BottomLayer w0.6: P1.2 55.841,-0.423 R13.2
NetQ6_1: Q6.1 R11.2 | length 1.9
  BottomLayer w0.4: Q6.1 47.504,8.421 R11.2
NetR8_2: R8.2 U6.8 | length 3.1
  BottomLayer w0.3: R8.2 54.063,10.1 U6.8
NetR20_1: R20.1 U15.12 | length 7.2
  BottomLayer w0.3: R20.1 8.229,18.225 11.675,18.225 12.15,18.7 U15.12
NetR23_1: R23.1 U1.10 | length 12.4
  BottomLayer w0.3: U1.10 6.005,-3.88 6.575,-4.45 15.986,-4.45 R23.1
NetR25_1: R25.1 U15.11 | length 4.9
  BottomLayer w0.3: R25.1@9.975,16.448 R25.1 10.001,17.226 10.375,17.6 12.025,17.6 12.8,18.375 U15.11
NetR76_2: R76.2 T1.2 | length 1.8
  BottomLayer w0.5: R76.2 37.727,24.038 T1.2
PH-INP: C32.1 C37.1 J1.2 U15.5 | length 8.2
  BottomLayer w0.4: J1.2 12.15,33.655 C32.1@12.15,28.282 ; U15.5 C32.1@12.15,28.282 ; C32.1 C32.1@12.15,28.282
PH-VCM: C32.2 C36.1 J2.3 U15.8 | length 55.4
  BottomLayer w0.4: C32.2 14.471,27.075 14.1,26.704 U15.8 15.875,25.6
  BottomLayer w0.5: C36.1 9.115,27.39 8.65,26.925 5.675,26.925 4.925,27.675 4.925,35.65 6.025,36.75 14.3,36.75 15.1,35.95 15.1,31.75 14.471,31.121 C32.2 ; 10.475,24.5 10.475,24.075 11.2,23.35 13.475,23.35 14.1,23.975 U15.8
  BottomLayer w0.6: 15.875,25.6 18.25,25.6 22.215,29.565 J2.3
RS485+: F10.2 J3.2 R18.1 | length 35.1
  TopLayer w0.3: v1(27.651,15.949) 27.651,25.501 31.5,29.35 40.425,29.35 42.545,31.47 J3.2
  BottomLayer w0.3: R18.1 v1(27.651,15.949)
  BottomLayer w0.6: J3.2 42.545,30.919 43.072,30.392 F10.2
RS485-: F11.2 J3.3 R19.1 | length 31.7
  TopLayer w0.3: v1(25.926,15.974) 25.926,25.051 31.15,30.275 35.775,30.275 37.465,31.965 J3.3
  BottomLayer w0.3: R19.1 v1(25.926,15.974)
  BottomLayer w0.6: F11.2 36.292,30.467 37.465,31.64 J3.3
RST#: C8.1 J9.15 R14.2 U2.4 | length 48.1
  TopLayer w0.3: v1(48.6,-5.155) 60.47,-5.155 64.125,-1.5 64.125,2.875 69.095,7.845 J9.15
  BottomLayer w0.3: C8.1 45.512,-8.824 R14.2 45.537,-8.218 v1(48.6,-5.155) 49,-4.755 U2.4
RX485: U2.10
SCK1: R10.2 U1.4 U2.12 | length 44.9
  TopLayer w0.3: v1(38.175,-7.8) 38.175,-6.125 v1(38.85,-5.45)
  BottomLayer w0.3: U1.4 9.815,-9.56 11.4,-7.975 19.1,-7.975 21.575,-5.5 38.825,-5.5 42.85,-1.475 U2.12 ; R10.2 v1(38.175,-7.8)
SPI_CS: U1.14 U5.3 | length 20.6
  BottomLayer w0.25: U5.3 5.739,9.939 3.6,7.8 3.6,3.775 5.275,2.1 9.025,2.1 11.085,0.04 U1.14
SPI_DIN: U1.12 U5.16 | length 11.7
  TopLayer w0.25: v3(8.025,2.775) 8.525,2.275 v3(8.525,-0.175)
  BottomLayer w0.25: U5.16 4.461,3.864 5.55,2.775 v3(8.025,2.775) ; v3(8.525,-0.175) 8.545,-0.195 U1.12
SPI_DOUT: U1.11 U5.15 | length 9.5
  TopLayer w0.25: v3(6.025,3.525) 7.225,2.325 v3(7.225,-0.075)
  BottomLayer w0.25: U5.15 5.111,4.439 v3(6.025,3.525) ; v3(7.225,-0.075) 7.225,-2.129 U1.11
SPI_SCLK: U1.13 U5.1 | length 19.9
  BottomLayer w0.3: U5.1 4.439,9.514 3.05,8.125 3.05,3.4 5.025,1.425 8.6,1.425 9.815,0.21 U1.13
SSEL1: R12.2 U1.3 U2.11 | length 42.7
  BottomLayer w0.25: U1.3 11.085,-9.64 12.075,-8.65 19.375,-8.65 21.8,-6.225 39.65,-6.225 40,-5.875 ; R12.2 40,-5.875 ; U2.11 43.9,-1.975 40,-5.875
TP+: J2.1 R3.1 R21.2 U5.11 | length 58
  BottomLayer w0.4: U5.11 7.711,9.286 9.35,10.925 19.15,10.925 22.675,14.45 22.675,23.075 25.325,25.725
  BottomLayer w0.6: R3.1 17.302,21.527 20.825,25.05 24.55,25.05 25.325,25.825 25.325,26.839 R21.2 ; R21.2@25.481,26.806 J2.1
TX485: U2.9
VCC3.3: C1.1 C3.2 C10.1 C11.1 C12.1 C13.1 C43.1 C44.1 CA1.1 CA13.1 CA14.1 FB7.2 J9.1 J9.2 P3V3.1 R1.1 R2.1 R4.1 R5.1 R6.1 R7.2 R9.1 R10.1 R12.1 R13.1 R14.1 R17.1 R22.1 U1.1 U2.1 U2.6 U2.19 U2.27 U12.2 U12.8 | length 80.4
  BottomLayer w0.3: C11.1 48,-4.343 U2.6 ; C13.1 45.779,4.151 46.5,3.43 U2.19 ; R7.2 46.663,13.887 47.025,13.525 47.025,12.5 47.586,11.939 FB7.2 ; U2.1 50.5,-3.85 53.638,-6.988 C10.1 ; U2.27 50.5,2.85 50.776,3.126 C12.1
  BottomLayer w0.5: U12.8 33.035,4.141 CA14.1 ; CA13.1@39.394,4.181 40.655,5.441 U12.2 ; R14.1 44.013,-8.33 C11.1 ; v1(51.724,18.799) R2.1 ; R13.1 v1(58.499,-0.426) ; R1.1 v1(66.837,-8.838) ; v1(75.301,20.501) R5.1 R4.1 ; v1(75.351,17.976) R17.1 ; R22.1 v1(76.303,11.378)
  BottomLayer w0.6: U1.1 14.8,-11.45 15.512,-10.738 C3.2 20.323,-9.214 CA1.1 23.889,-9.214 25.15,-10.475 v1(33.275,-10.475) R9.1 R6.1 R10.1 R12.1 ; v1(43.026,-8.799) R14.1
  BottomLayer w0.8: v1(33.226,2.526) CA14.1 ; v1(39.389,2.586) CA13.1
  BottomLayer w1: CA14.1@32.975,3.699 CA14.1 ; FB7.2 49.7,11.364 P3V3.1
  other v1: 53.825,-6.95 52.975,3.15 46.475,3.325
VCC_COM: C45.1 C46.2 CA15.1 CA16.1 R41.1 U12.12 U12.19 | length 19.8
  BottomLayer w0.5: CA15.1 25.301,17.963 C45.1 28.012,17.525 31.4,17.525 31.765,17.89 U12.12 ; R41.1 40.655,22.132 U12.19 40.655,17.92 41.3,17.275 42.9,17.275 43.563,17.938 CA16.1@47.125,17.938
  other v1: 28.875,17.525 45.65,17.95 40.625,20.875
VDD_ISO: C2.1 C6.1 C14.1 C25.1 CA2.1 FB1.1 R23.2 U1.16 U5.13 U7.3 U15.1 U15.14 | length 29.6
  BottomLayer w0.3: U5.13 6.411,5.314 7.25,4.475 11.011,4.475 C14.1
  BottomLayer w0.4: v1(4.862,25.612) C25.1 ; C25.1@6.813,25.6 U15.1 ; v1(10.3,20.525) 10.6,20.525 10.85,20.275 U15.14 ; CA2.1@14.836,1.8 CA2.1@14.836,2.214
  BottomLayer w0.5: CA2.1 14.836,0.386 13.625,-0.825 U1.16 14.034,-2.588 R23.2 ; CA2.1@14.836,1.8 14.9,1.736 14.9,1.712 C2.1 C6.1 18.915,1.726 20.768,1.726 U7.3 ; v1(19.25,3.075) 19.25,4.862 FB1.1 ; C6.1@19.274,1.945 v1@19.274,3.075
  other v1: 16.175,1.7 17.975,1.75 10.425,4.525
VREF: C33.1 C35.1 FB2.2 U5.9 U15.9 | length 28.1
  TopLayer w0.5: v1(14.5,16.45) 14.5,10.475 v1(15.575,9.4)
  BottomLayer w0.3: U5.9 9.011,7.561 9.625,8.175 C35.1@11.249,8.175
  BottomLayer w0.35: C33.1 13.526,17.526 14.1,18.1 U15.9
  BottomLayer w0.5: C35.1 12.513,8.163 13.75,9.4 20.425,9.4 21.024,8.801 FB2.2 ; C33.1 14.462,16.412 v1(14.5,16.45)
pads on no net: J9.11 J9.17 J9.19 U1.7 U2.7 U2.15 U2.16 U2.20 U2.32 U2.33 U2.34 U5.2 U5.4 U6.7 U6.9 U15.2 U15.3 U15.7

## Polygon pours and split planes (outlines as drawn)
GND_ISO on BottomLayer "BottomLayer-No Net" (hatched 90Degree grid 0.3 track 0.3, remove dead copper, pour order 5): -1.45,21.2 23.425,21.2 23.5,21.275 23.5,1.05 20.325,-2.125 17.475,-4.975 3.5,-4.975 3.5,2.7 -1.45,7.65
GND on BottomLayer "BottomLayer-No Net" (hatched 90Degree grid 0.3 track 0.3, remove dead copper, pour order 9): -1.175,-6.925 17.95,-6.925 25.375,0.5 25.6,0.725 25.6,12.7 47.2,12.7 47.5,12.4 47.5,8.675 48.875,7.3 49.325,6.85 69.475,6.85 69.475,-13.85 69.55,-13.925 -1.075,-13.925 -1.175,-13.825
GND on TopLayer "BottomLayer-No Net" (hatched 90Degree grid 0.3 track 0.3, remove dead copper, pour order 3): -0.5,-6.825 17.975,-6.825 25.55,0.75 25.55,12.525 25.7,12.675 47.275,12.675 47.575,12.375 47.575,8.525 49.35,6.75 69.525,6.75 69.525,-13.575 69.675,-13.725 -1.025,-13.725 -1.15,-13.6 -1.15,-6.825
GND_ISO on TopLayer "BottomLayer-No Net" (hatched 90Degree grid 0.3 track 0.3, remove dead copper, pour order 7): -1.475,21.25 23.25,21.25 23.4,21.1 23.4,1.225 17.675,-4.5 17.25,-4.925 3.525,-4.925 3.525,2.725 -1.475,7.725
GND_COM on GND (split plane): 49.923,18.566 46.109,14.752 25.002,14.752 25.002,22.009 35.234,32.241 35.284,32.302 35.321,32.371 35.344,32.447 35.352,32.525 35.352,43.115 49.923,43.115
GND_ISO on GND (split plane): 34.548,32.691 24.316,22.459 24.266,22.398 24.229,22.329 24.206,22.253 24.198,22.175 24.198,8.5 24.198,1.391 17.459,-5.348 -11.59,-5.348 -11.59,43.115 4.7,43.115 4.7,32 4.75,31.95 9.925,31.95 10.425,31.45 10.425,22.9 10.45,22.925 16,22.925 16.075,23 16.075,43.115 34.548,43.115
GND on GND (split plane): 84.865,28.627 77.675,28.627 77.597,28.619 77.539,28.602 77.521,28.596 77.452,28.559 77.391,28.509 72.816,23.934 72.766,23.873 72.729,23.804 72.706,23.728 72.698,23.65 72.698,8.377 52.55,8.377 52.472,8.369 52.396,8.346 52.327,8.309 52.266,8.259 52.216,8.198 52.179,8.129 52.156,8.053 52.148,7.975 52.156,7.897 52.179,7.821 52.216,7.752 52.266,7.691 52.327,7.641 52.396,7.604 52.472,7.581 52.55,7.573 73.1,7.573 73.178,7.581 73.254,7.604 73.323,7.641 73.384,7.691 73.434,7.752 73.471,7.821 73.494,7.897 73.502,7.975 73.502,23.484 77.841,27.823 84.865,27.823 84.865,-13.315 -11.59,-13.315 -11.59,-6.152 17.625,-6.152 17.703,-6.144 17.779,-6.121 17.848,-6.084 17.909,-6.034 24.884,0.941 24.934,1.002 24.971,1.071 24.977,1.089 24.994,1.147 25.002,1.225 25.002,8.5 25.002,13.948 46.275,13.948 46.353,13.956 46.429,13.979 46.498,14.016 46.559,14.066 50.609,18.116 50.659,18.177 50.696,18.246 50.719,18.322 50.727,18.4 50.727,43.115 84.865,43.115
VCC_COM on PWR (split plane): 49.898,20.788 49.866,20.748 49.829,20.679 49.806,20.603 49.798,20.525 49.806,20.447 49.829,20.371 49.866,20.302 49.898,20.262 49.898,18.516 46.209,14.827 25.052,14.827 25.052,22.034 35.234,32.216 35.284,32.277 35.321,32.346 35.344,32.422 35.352,32.5 35.352,43.115 49.898,43.115
+24V on PWR (split plane): 84.865,28.627 77.725,28.627 77.647,28.619 77.571,28.596 77.502,28.559 77.441,28.509 72.791,23.859 72.741,23.798 72.704,23.729 72.681,23.653 72.673,23.575 72.673,8.302 52.852,8.302 52.852,12.934 54.784,14.866 54.834,14.927 54.871,14.996 54.894,15.072 54.902,15.15 54.902,20.525 54.894,20.603 54.871,20.679 54.834,20.748 54.784,20.809 54.723,20.859 54.654,20.896 54.578,20.919 54.5,20.927 50.702,20.927 50.702,43.115 84.865,43.115
VDD_ISO on PWR (split plane): 34.548,32.666 24.366,22.484 24.316,22.423 24.279,22.354 24.256,22.278 24.248,22.2 24.248,1.441 17.509,-5.298 -11.59,-5.298 -11.59,43.115 4.6,43.115 4.6,31.925 10,31.925 10.425,31.5 10.425,22.925 16.075,22.925 16.125,22.975 16.125,43.115 34.548,43.115
VCC3.3 on PWR (split plane): 84.865,-13.315 -11.59,-13.315 -11.59,-6.102 17.675,-6.102 17.753,-6.094 17.829,-6.071 17.898,-6.034 17.959,-5.984 24.934,0.991 24.984,1.052 25.021,1.121 25.044,1.197 25.052,1.275 25.052,14.023 46.375,14.023 46.453,14.031 46.529,14.054 46.598,14.091 46.659,14.141 50.584,18.066 50.634,18.127 50.671,18.196 50.694,18.272 50.702,18.35 50.702,20.123 54.098,20.123 54.098,15.316 52.166,13.384 52.116,13.323 52.079,13.254 52.056,13.178 52.048,13.1 52.048,7.9 52.056,7.822 52.079,7.746 52.116,7.677 52.166,7.616 52.227,7.566 52.296,7.529 52.372,7.506 52.45,7.498 73.075,7.498 73.153,7.506 73.229,7.529 73.298,7.566 73.359,7.616 73.409,7.677 73.446,7.746 73.469,7.822 73.477,7.9 73.477,23.409 77.891,27.823 84.865,27.823

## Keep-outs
KeepOutLayer:
  lines w0.3: 16.125,28.675 16.125,44.6 ; 16.15,28.675 ccw(c17.868,29.213) 19.586,28.675 ; 19.572,28.625 19.572,44.325 ; 24,28.7 24,45.925 ; 24.025,28.7 ccw(c24.638,28.892) 25.25,28.7 25.25,45.85
  lines w0.5: -7.235,-4.177 cw(c-7.38,-9.155) -2.402,-9.01 ; -7.235,-4.175 -12.1,-4.175 -12.1,33.825 -7.235,33.825 ; -7.235,33.827 ccw(c-7.38,38.805) -2.402,38.66 ; -2.425,-9.01 -2.425,-13.825 75.6,-13.825 75.6,-9.355 ; -2.4,38.66 -2.4,43.65 75.575,43.65 75.575,38.966 ; 75.602,-9.21 cw(c80.58,-9.355) 80.435,-4.377 ; 75.603,38.817 ccw(c80.716,38.966) 80.567,33.852 ; 80.58,-4.375 85.375,-4.375 85.375,33.85 80.716,33.85

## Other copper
GND (plane layer: these items are gaps in the copper):
  pour cut-out: 16.075,44.35 16.075,23 16,22.925 10.45,22.925 10.425,22.9 10.425,31.45 9.925,31.95 4.75,31.95 4.7,32 4.7,44.15 4.875,44.325
  lines w0.8: -12.1,-5.75 16.825,-5.75 17.625,-5.75 24.6,1.225 24.6,8.5 24.6,22.175 34.95,32.525 34.95,43.775 ; 24.6,14.35 46.275,14.35 50.325,18.4 50.325,43.725 ; 52.55,7.975 73.1,7.975 73.1,23.65 77.675,28.225 85.675,28.225
PWR (plane layer: these items are gaps in the copper):
  pour cut-out: 16.125,44.6 16.125,22.975 16.075,22.925 10.425,22.925 10.425,31.5 10,31.925 4.6,31.925 4.6,44.55 4.65,44.6
  lines w0.8: -12.15,-5.7 17.675,-5.7 24.65,1.275 24.65,22.2 34.95,32.5 34.95,43.675 ; 24.675,14.425 46.375,14.425 50.3,18.35 50.3,43.7 ; 50.2,20.525 54.5,20.525 54.5,15.15 52.45,13.1 52.45,7.9 73.075,7.9 73.075,23.575 77.725,28.225 85.475,28.225

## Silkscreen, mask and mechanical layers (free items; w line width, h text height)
TopOverlay:
  text "GUARD  INP" at 5.45,28.475 h1
  text "- RS485 +   PE" at 35.95,28.375 h1
  text "+24V   GND   PE" at 50.675,28.275 h1
  text "VCM  - Temp +" at 21.4,28.175 h1
  text "SPMsensor_RS485" at -5.325,7.975 h1.2 r90
  text "JTAG" at 76.825,5.525 h0.8 r270
Mechanical1:
  lines w0.25: -14.175,30 76.025,30 ; -13.4,33.675 76.8,33.675 ; -13.15,0 87.65,0 ; 0,-4.9 0,36.6 ; 72.95,-5.025 72.95,45.8
  lines w0.254: -12.925,43.65 87.175,43.65 ; -12.096,-13.814 88.414,-13.814 ; 6.975,26.45 6.975,42.85 ; 85.375,-12.675 85.375,46.95
  lines w0.3: -12.094,-18.55 -12.094,55.4 ; 56.2,-30.025 56.2,46.1

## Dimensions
-13.725,15 to -13.125,0 on Mechanical1
-13.175,-13.816 to -14.15,15 on Mechanical1
0,-3.2 to 72.95,-3.875 on Mechanical1
-12.096,-13.814 to 85.375,-12.675 on Mechanical1
-12.096,-13.814 to -12.925,43.65 on Mechanical1
6.975,42.325 to 0,34.1 on Mechanical1
-12.975,43.675 to -12.7,33.675 on Mechanical1
-13.725,30 to -13.125,15 on Mechanical1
